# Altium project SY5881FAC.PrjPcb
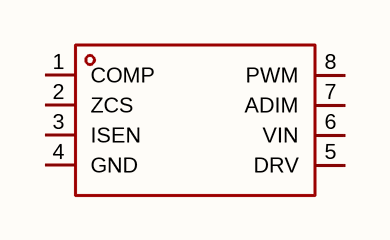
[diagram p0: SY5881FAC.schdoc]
1 sheet, 1 parts. Net scope: global (net labels, ports and power ports of the same name join across sheets).

## Sheet SY5881FAC.schdoc
size 127 x 101 mm

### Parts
U?  sy5881fac  [SOP-8_L4.9-W3.9-P1.27-LS6.0-BL]  (value not drawn)

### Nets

Not connected (* = marked no-connect by the designer): U? 1(COMP) 2(ZCS) 3(ISEN) 4(GND) 5(DRV) 6(VIN) 7(ADIM) 8(PWM)

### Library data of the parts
U? = sy5881fac: 类型:-;工作电压(DC):8V~20V;开关频率:46kHz~120kHz;通道数:1;输出电压:-;输出电流:300mA;调光:PWM；模拟;拓扑结构:降压;; Manufacturer: Silergy(矽力杰); AddInBom: yes; ModelId: 75c24a7891ee4dd6bdac16a7163ff87e; ModelName: SOP-8_L4.9-W3.9-P1.27-LS6.0-BL-1; ModelTransform: 192.913,236.22,0,0,0,0,-0.393,2.749,0; Voltage - Input(DC): 8V~20V; Number of Channels: 1; Output Current: 300mA; Dimming: PWM；模拟; Topology: 降压; Switch Tube (Built-In/External): 外置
